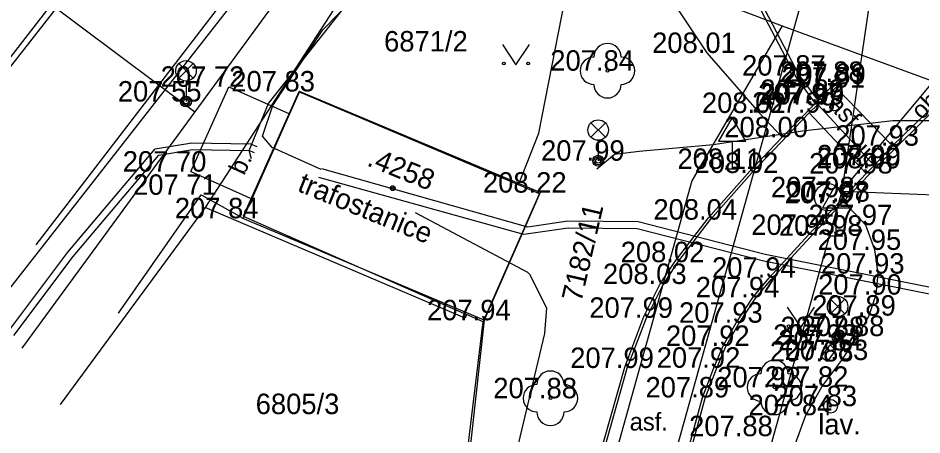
# Model space of a CAD drawing. Extents: x -524633 to -524336, y -1187893 to -1187683.
# Drawn here: x -524616 to -524582.86, y -1187820.09 to -1187804.81 of the extents above; entities that cross this region are included whole.
import ezdxf

# ---------------------------------------------------------------- set-up
doc = ezdxf.new("R2010")
doc.units = 0
for name, color, linetype in [('Hranice parcel', 7, 'Continuous'), ('Parcelní čísla', 7, 'Continuous'), ('Vrstva 1', 7, 'Continuous'), ('Vrstva 10', 7, 'Continuous'), ('Vrstva 11', 7, 'Continuous'), ('Vrstva 22', 7, 'Continuous'), ('Vrstva 24', 7, 'Continuous'), ('Vrstva 25', 7, 'Continuous'), ('Vrstva 27', 7, 'Continuous'), ('Vrstva 3', 7, 'Continuous'), ('Vrstva 33', 7, 'Continuous'), ('Vrstva 34', 7, 'Continuous'), ('Vrstva 36', 7, 'Continuous'), ('Vrstva 39', 7, 'Continuous'), ('Vrstva 4', 7, 'Continuous'), ('Vrstva 40', 7, 'Continuous'), ('Vrstva 41', 7, 'Continuous'), ('Vrstva 5', 7, 'Continuous'), ('Vrstva 52', 7, 'Continuous'), ('Vrstva 54', 7, 'Continuous'), ('Vrstva 55', 7, 'Continuous'), ('Vrstva 56', 7, 'Continuous'), ('Vrstva 7', 7, 'Continuous')]:
    doc.layers.add(name, color=color, linetype=linetype)

msp = doc.modelspace()

# ---------------------------------------------------------------- linework, layer by layer
at = {"layer": 'Hranice parcel'}
for p, q in [((-524601.49, -1187799.98), (-524609.14, -1187811.75)), ((-524595.57, -1187802.22), (-524587.98, -1187805.09)), ((-524587.98, -1187805.09), (-524591.3, -1187810.78)), ((-524609.14, -1187811.75), (-524614.452, -1187818.979)), ((-524599.61, -1187815.81), (-524609.14, -1187811.75)), ((-524599.56, -1187815.68), (-524599.61, -1187815.81)), ((-524598.94, -1187815.95), (-524599.56, -1187815.68))]:
    msp.add_line(p, q, dxfattribs=at)
for points in [[(-524587.98, -1187805.09), (-524567.6, -1187812.58), (-524548.29, -1187760.37)], [(-524597.65, -1187810.93), (-524596.9, -1187809.03), (-524595.57, -1187802.22)], [(-524597.65, -1187810.93), (-524605.7, -1187807.52), (-524607.75, -1187812.07), (-524599.56, -1187815.68)], [(-524591.3, -1187810.78), (-524596.74, -1187830.3), (-524599.279, -1187841.552)], [(-524598.94, -1187815.95), (-524596.88, -1187811.26), (-524597.65, -1187810.93)], [(-524601.622, -1187838.066), (-524598.94, -1187815.95)]]:
    msp.add_lwpolyline(points, dxfattribs=at)
at = {"layer": 'Vrstva 1'}
for p, q in [((-524590.75, -1187806.09), (-524590.75, -1187806.09)), ((-524594.39, -1187806.74), (-524594.39, -1187806.74)), ((-524587.36, -1187806.92), (-524587.36, -1187806.92)), ((-524585.97, -1187807.15), (-524585.97, -1187807.15)), ((-524585.89, -1187807.23), (-524585.89, -1187807.23)), ((-524608.27, -1187807.33), (-524608.27, -1187807.33)), ((-524605.68, -1187807.5), (-524605.68, -1187807.5)), ((-524586.01, -1187807.36), (-524586.01, -1187807.36)), ((-524609.84, -1187807.87), (-524609.84, -1187807.87)), ((-524586.69, -1187807.81), (-524586.69, -1187807.81)), ((-524586.77, -1187807.94), (-524586.77, -1187807.94)), ((-524586.68, -1187807.98), (-524586.68, -1187807.98)), ((-524588.83, -1187808.29), (-524588.83, -1187808.29)), ((-524586.99, -1187808.28), (-524586.99, -1187808.28)), ((-524587.98, -1187809.18), (-524587.98, -1187809.18)), ((-524583.94, -1187809.49), (-524583.94, -1187809.49)), ((-524594.73, -1187810.04), (-524594.73, -1187810.04)), ((-524584.61, -1187810.21), (-524584.61, -1187810.21)), ((-524609.66, -1187810.44), (-524609.66, -1187810.44)), ((-524589.82, -1187810.34), (-524589.82, -1187810.34)), ((-524589.1, -1187810.49), (-524589.1, -1187810.49)), ((-524584.9, -1187810.51), (-524584.9, -1187810.51)), ((-524584.59, -1187810.32), (-524584.59, -1187810.32)), ((-524596.86, -1187811.21), (-524596.86, -1187811.21)), ((-524609.28, -1187811.29), (-524609.28, -1187811.29)), ((-524586.3, -1187811.38), (-524586.3, -1187811.38)), ((-524585.74, -1187811.54), (-524585.74, -1187811.54)), ((-524585.8, -1187811.6), (-524585.8, -1187811.6)), ((-524607.75, -1187812.15), (-524607.75, -1187812.15)), ((-524590.61, -1187812.2), (-524590.61, -1187812.2)), ((-524584.92, -1187812.4), (-524584.92, -1187812.4)), ((-524587.02, -1187812.76), (-524587.02, -1187812.76)), ((-524586.01, -1187812.79), (-524586.01, -1187812.79)), ((-524584.59, -1187813.31), (-524584.59, -1187813.31)), ((-524591.81, -1187813.76), (-524591.81, -1187813.76)), ((-524584.47, -1187814.18), (-524584.47, -1187814.18)), ((-524588.46, -1187814.33), (-524588.46, -1187814.33)), ((-524592.46, -1187814.56), (-524592.46, -1187814.56)), ((-524589.06, -1187815.05), (-524589.06, -1187815.05)), ((-524584.54, -1187814.95), (-524584.54, -1187814.95)), ((-524592.96, -1187815.8), (-524592.96, -1187815.8)), ((-524584.79, -1187815.72), (-524584.79, -1187815.72)), ((-524598.91, -1187815.89), (-524598.91, -1187815.89)), ((-524589.67, -1187815.98), (-524589.67, -1187815.98)), ((-524585.95, -1187816.51), (-524585.95, -1187816.51)), ((-524585.21, -1187816.47), (-524585.21, -1187816.47)), ((-524590.15, -1187816.83), (-524590.15, -1187816.83)), ((-524586.22, -1187816.79), (-524586.22, -1187816.79)), ((-524586.03, -1187816.99), (-524586.03, -1187816.99)), ((-524586.34, -1187817.4), (-524586.34, -1187817.4)), ((-524585.8, -1187817.35), (-524585.8, -1187817.35)), ((-524593.66, -1187817.64), (-524593.66, -1187817.64)), ((-524590.49, -1187817.63), (-524590.49, -1187817.63)), ((-524588.27, -1187818.35), (-524588.27, -1187818.35)), ((-524586.53, -1187818.33), (-524586.53, -1187818.33)), ((-524596.48, -1187818.75), (-524596.48, -1187818.75)), ((-524590.9, -1187818.72), (-524590.9, -1187818.72)), ((-524586.21, -1187819.04), (-524586.21, -1187819.04)), ((-524587.12, -1187819.37), (-524587.12, -1187819.37))]:
    msp.add_line(p, q, dxfattribs=at)
at = {"layer": 'Vrstva 10'}
msp.add_line((-524619.041, -1187810.134), (-524610.724, -1187799.471), dxfattribs=at)
msp.add_lwpolyline([(-524607.4, -1187802.77), (-524615.342, -1187813.119)], dxfattribs=at)
at = {"layer": 'Vrstva 11'}
for p, q in [((-524580.79, -1187806.59), (-524584.589, -1187810.32)), ((-524609.66, -1187810.44), (-524608.27, -1187807.33)), ((-524608.27, -1187807.33), (-524606.045, -1187808.32)), ((-524609.66, -1187810.44), (-524607.431, -1187811.432))]:
    msp.add_line(p, q, dxfattribs=at)
for points in [[(-524597.4, -1187786.99), (-524593.539, -1187788.69), (-524593.099, -1187788.98), (-524592.909, -1187789.29), (-524592.87, -1187789.86), (-524593.639, -1187794.38), (-524593.659, -1187797.63), (-524593.279, -1187800.17), (-524592.58, -1187802.84), (-524591.989, -1187804.22), (-524590.75, -1187806.09), (-524588.83, -1187808.29), (-524587.979, -1187809.18)], [(-524584.279, -1187790.1), (-524589.16, -1187788.08), (-524589.906, -1187790.567), (-524590.419, -1187792.88), (-524590.639, -1187795.377), (-524590.669, -1187795.92), (-524590.54, -1187798.155), (-524589.955, -1187801.184), (-524589.619, -1187802.37), (-524588.89, -1187804.282), (-524587.47, -1187806.99), (-524586.77, -1187807.94), (-524586.68, -1187807.98), (-524586.01, -1187807.36), (-524585.889, -1187807.23), (-524585.969, -1187807.15)], [(-524584.17, -1187790.25), (-524589.08, -1187788.28), (-524589.78, -1187790.6), (-524590.29, -1187792.9), (-524590.509, -1187795.38), (-524590.511, -1187795.93), (-524590.41, -1187798.14), (-524589.829, -1187801.15), (-524589.46, -1187802.35), (-524588.77, -1187804.23), (-524587.36, -1187806.92), (-524586.689, -1187807.81), (-524585.969, -1187807.15)], [(-524580.79, -1187806.44), (-524583.939, -1187809.49)], [(-524583.939, -1187809.49), (-524586.01, -1187807.36)], [(-524598.029, -1187833.73), (-524596.837, -1187828.956), (-524596.356, -1187826.935), (-524595.036, -1187822.133), (-524593.755, -1187817.609), (-524593.05, -1187815.757), (-524592.459, -1187814.56), (-524591.894, -1187813.705), (-524590.686, -1187812.136), (-524589.173, -1187810.422), (-524587.979, -1187809.18), (-524586.77, -1187807.94)], [(-524597.94, -1187833.75), (-524596.74, -1187828.98), (-524596.259, -1187826.96), (-524594.94, -1187822.16), (-524593.66, -1187817.64), (-524592.959, -1187815.8), (-524592.367, -1187814.624), (-524591.81, -1187813.76), (-524590.609, -1187812.2), (-524589.099, -1187810.49), (-524586.99, -1187808.28), (-524586.68, -1187807.98)], [(-524584.609, -1187810.21), (-524586.68, -1187807.98)], [(-524586.99, -1187808.28), (-524584.899, -1187810.51)], [(-524583.939, -1187809.49), (-524584.609, -1187810.21)], [(-524584.609, -1187810.21), (-524584.9, -1187810.51)], [(-524595.18, -1187835.03), (-524592.989, -1187826.37), (-524590.899, -1187818.72), (-524590.489, -1187817.63), (-524590.149, -1187816.83), (-524589.669, -1187815.98), (-524589.059, -1187815.05), (-524588.459, -1187814.33), (-524587.019, -1187812.76), (-524584.9, -1187810.51)], [(-524595.083, -1187835.055), (-524594.02, -1187830.84), (-524593.84, -1187830.05), (-524593.019, -1187826.95), (-524592.893, -1187826.395), (-524590.804, -1187818.751), (-524590.396, -1187817.667), (-524590.059, -1187816.874), (-524589.584, -1187816.032), (-524588.979, -1187815.11), (-524588.384, -1187814.396), (-524586.946, -1187812.828), (-524585.8, -1187811.6), (-524585.74, -1187811.54), (-524584.59, -1187810.32)], [(-524584.369, -1187831.42), (-524584.929, -1187831), (-524585.72, -1187830.12), (-524586.199, -1187829.49), (-524586.74, -1187828.64), (-524587.34, -1187827.39), (-524587.86, -1187825.74), (-524588.049, -1187824.24), (-524588.05, -1187822.96), (-524587.9, -1187821.8), (-524587.69, -1187820.95), (-524587.119, -1187819.37), (-524586.53, -1187818.33), (-524585.8, -1187817.35), (-524585.209, -1187816.47), (-524584.789, -1187815.72), (-524584.539, -1187814.95), (-524584.469, -1187814.18), (-524584.59, -1187813.31), (-524584.92, -1187812.4), (-524585.739, -1187811.54)]]:
    msp.add_lwpolyline(points, dxfattribs=at)
at = {"layer": 'Vrstva 22'}
for centre in [(-524594.389, -1187806.74), (-524588.269, -1187818.35), (-524596.48, -1187818.75)]:
    msp.add_circle(centre, 0.05, dxfattribs=at)
for centre, start, end in [((-524594.389, -1187806.24), 0, 180), ((-524594.889, -1187806.74), 90, 270), ((-524593.889, -1187806.74), 270, 90), ((-524594.389, -1187807.24), 180, 0), ((-524588.269, -1187817.85), 0, 180), ((-524596.48, -1187818.25), 0, 180), ((-524588.769, -1187818.35), 90, 270), ((-524587.769, -1187818.35), 270, 90), ((-524596.98, -1187818.75), 90, 270), ((-524595.98, -1187818.75), 270, 90), ((-524588.269, -1187818.85), 180, 0), ((-524596.48, -1187819.25), 180, 0)]:
    msp.add_arc(centre, 0.5, start, end, dxfattribs=at)
at = {"layer": 'Vrstva 24'}
msp.add_lwpolyline([(-524586.219, -1187816.79), (-524586.029, -1187816.99), (-524586.339, -1187817.4), (-524586.553, -1187817.242), (-524586.219, -1187816.79)], dxfattribs=at)
at = {"layer": 'Vrstva 25'}
for radius in [0.25, 0.0303]:
    msp.add_circle((-524586.209, -1187819.04), radius, dxfattribs=at)
at = {"layer": 'Vrstva 27'}
msp.add_circle((-524586.299, -1187811.38), 0.5, dxfattribs=at)
at = {"layer": 'Vrstva 33'}
for p, q in [((-524610.105, -1187807.01), (-524609.575, -1187806.48)), ((-524610.105, -1187806.48), (-524609.575, -1187807.01)), ((-524609.84, -1187807.12), (-524609.84, -1187807.87)), ((-524594.995, -1187809.18), (-524594.465, -1187808.65)), ((-524594.995, -1187808.65), (-524594.465, -1187809.18)), ((-524594.73, -1187809.29), (-524594.73, -1187810.04)), ((-524586.214, -1187815.65), (-524585.684, -1187815.12)), ((-524586.214, -1187815.12), (-524585.684, -1187815.65)), ((-524585.949, -1187815.76), (-524585.949, -1187816.51))]:
    msp.add_line(p, q, dxfattribs=at)
for centre, radius in [((-524609.84, -1187806.745), 0.375), ((-524609.84, -1187807.87), 0.2), ((-524609.84, -1187807.87), 0.145), ((-524609.84, -1187807.87), 0.0876), ((-524594.73, -1187808.915), 0.375), ((-524594.73, -1187810.04), 0.2), ((-524594.73, -1187810.04), 0.145), ((-524594.73, -1187810.04), 0.0876), ((-524585.949, -1187815.385), 0.375), ((-524585.949, -1187816.51), 0.2), ((-524585.949, -1187816.51), 0.145), ((-524585.949, -1187816.51), 0.0876)]:
    msp.add_circle(centre, radius, dxfattribs=at)
at = {"layer": 'Vrstva 34'}
for p, q in [((-524589.82, -1187809.322), (-524589.82, -1187810.34)), ((-524590.07, -1187810.34), (-524589.57, -1187810.34)), ((-524586.01, -1187811.772), (-524586.01, -1187812.79)), ((-524586.26, -1187812.79), (-524585.76, -1187812.79))]:
    msp.add_line(p, q, dxfattribs=at)
for points in [[(-524590.32, -1187809.322), (-524589.32, -1187809.322), (-524589.82, -1187808.456)], [(-524586.51, -1187811.772), (-524585.51, -1187811.772), (-524586.01, -1187810.906)]]:
    msp.add_lwpolyline(points, close=True, dxfattribs=at)
at = {"layer": 'Vrstva 36'}
for points in [[(-524598.242, -1187805.778), (-524597.742, -1187806.528), (-524597.242, -1187805.778)], [(-524587.795, -1187815.407), (-524587.295, -1187816.157), (-524586.795, -1187815.407)]]:
    msp.add_lwpolyline(points, dxfattribs=at)
for centre in [(-524598.192, -1187806.477), (-524597.293, -1187806.477), (-524587.746, -1187816.107), (-524586.846, -1187816.107)]:
    msp.add_circle(centre, 0.05, dxfattribs=at)
at = {"layer": 'Vrstva 39'}
for radius in [0.09, 0.0398]:
    msp.add_circle((-524602.262, -1187811.048), radius, dxfattribs=at)
at = {"layer": 'Vrstva 5'}
for p, q in [((-524596.859, -1187811.21), (-524605.68, -1187807.5)), ((-524596.859, -1187811.21), (-524598.91, -1187815.89)), ((-524598.91, -1187815.89), (-524607.781, -1187812.15))]:
    msp.add_line(p, q, dxfattribs=at)
msp.add_lwpolyline([(-524605.68, -1187807.5), (-524606.045, -1187808.32), (-524607.431, -1187811.432), (-524607.75, -1187812.15)], dxfattribs=at)
at = {"layer": 'Vrstva 52'}
for points in [[(-524604.888, -1187810.358), (-524606.68, -1187809.553), (-524607.041, -1187809.142), (-524606.651, -1187808.01), (-524604.828, -1187805.241), (-524602.389, -1187802.751), (-524595.518, -1187792.842), (-524592.363, -1187786.571), (-524587.685, -1187773.341), (-524584.851, -1187764.936), (-524580.85, -1187751.486), (-524581.943, -1187749.433), (-524589.511, -1187743.31), (-524591.925, -1187742.225), (-524592.398, -1187741.002), (-524589.2, -1187727.331), (-524588.107, -1187723.138), (-524586.572, -1187712.872)], [(-524607.441, -1187809.976), (-524607.53, -1187809.669), (-524606.817, -1187807.941), (-524600.734, -1187800.222), (-524596.921, -1187794.77), (-524594.569, -1187790.848), (-524590.203, -1187780.476), (-524585.928, -1187767.436), (-524582.597, -1187756.424), (-524580.946, -1187751.47), (-524581.141, -1187750.169), (-524583.06, -1187749.051), (-524585.106, -1187746.981), (-524589.425, -1187743.717), (-524592.03, -1187742.347), (-524592.569, -1187741.747), (-524592.712, -1187740.711), (-524590.247, -1187725.964), (-524590.389, -1187724.462)], [(-524561.344, -1187803.955), (-524561.158, -1187804.072), (-524561.105, -1187804.363), (-524560.563, -1187805.046), (-524565.022, -1187808.878), (-524568.246, -1187812.343), (-524571.77, -1187815.678), (-524574.968, -1187815.882), (-524582.642, -1187814.923), (-524588.661, -1187813.718), (-524593.294, -1187812.534), (-524595.823, -1187812.509), (-524597.459, -1187812.746), (-524604.971, -1187810.656)], [(-524594.78, -1187810.34), (-524594.13, -1187809.8), (-524593.22, -1187809.69), (-524590.51, -1187809.44), (-524587.24, -1187808.95), (-524583.93, -1187808.57), (-524582.42, -1187808.56)], [(-524594.78, -1187810.34), (-524594.13, -1187809.8), (-524593.22, -1187809.69), (-524590.51, -1187809.44), (-524587.24, -1187808.95), (-524583.93, -1187808.57), (-524582.42, -1187808.56)], [(-524616.301, -1187816.226), (-524614.173, -1187813.398), (-524610.969, -1187809.609), (-524609.623, -1187809.38), (-524607.479, -1187809.42), (-524607.248, -1187809.513)], [(-524616.154, -1187816.446), (-524613.978, -1187813.554), (-524610.837, -1187809.84), (-524609.604, -1187809.63), (-524607.53, -1187809.669), (-524607.344, -1187809.744)], [(-524582.602, -1187814.676), (-524588.605, -1187813.474), (-524593.261, -1187812.284), (-524595.84, -1187812.259), (-524597.308, -1187812.473), (-524604.865, -1187810.336)], [(-524601.437, -1187811.944), (-524597.315, -1187814.128), (-524597.244, -1187814.198), (-524596.619, -1187815.437), (-524596.693, -1187816.369), (-524597.904, -1187821.455), (-524598.998, -1187827.91), (-524599.45, -1187831), (-524600.062, -1187834.455), (-524600.26, -1187836.252), (-524600.682, -1187839.465)]]:
    msp.add_lwpolyline(points, dxfattribs=at)
at = {"layer": 'Vrstva 54'}
for p, q in [((-524615.844, -1187816.907), (-524598.973, -1187793.847)), ((-524609.518, -1187808.261), (-524617.317, -1187802.419))]:
    msp.add_line(p, q, dxfattribs=at)
at = {"layer": 'Vrstva 55'}
for p, q in [((-524585.8, -1187811.16), (-524537.22, -1187752.94)), ((-524604.019, -1187798.98), (-524616.853, -1187815.406)), ((-524586.38, -1187800.98), (-524594.57, -1187830.29)), ((-524584.4, -1187801.59), (-524585.8, -1187811.16)), ((-524585.8, -1187811.16), (-524595.769, -1187846.775)), ((-524585.8, -1187811.16), (-524580.804, -1187811.357))]:
    msp.add_line(p, q, dxfattribs=at)
at = {"layer": 'Vrstva 56'}
msp.add_lwpolyline([(-524586.54, -1187727.18), (-524588.97, -1187737.12), (-524590.36, -1187742.45), (-524593, -1187751.96), (-524600.51, -1187779.94), (-524604.9, -1187791.29), (-524607.89, -1187795.49), (-524608.098, -1187795.783), (-524608.38, -1187796.18), (-524608.59, -1187796.44), (-524610.16, -1187798.34), (-524617.66, -1187808), (-524619.897, -1187810.877)], dxfattribs=at)
at = {"layer": 'Vrstva 7'}
for p, q in [((-524612.317, -1187815.63), (-524609.28, -1187811.29)), ((-524609.28, -1187811.29), (-524607.75, -1187812.15))]:
    msp.add_line(p, q, dxfattribs=at)
msp.add_lwpolyline([(-524598.91, -1187815.89), (-524599.739, -1187823.43)], dxfattribs=at)

# ---------------------------------------------------------------- texts
at = {"layer": 'Parcelní čísla'}
for s, p in [('6871/2', (-524602.578, -1187806.035)), ('6805/3', (-524607.285, -1187819.33))]:
    msp.add_text(s, height=0.75, dxfattribs=at).set_placement(p)
for s, rotation, p in [('.4258', 338, (-524603.244, -1187810.205)), ('7182/11', 77, (-524595.346, -1187815.25))]:
    msp.add_text(s, height=0.75, rotation=rotation, dxfattribs=at).set_placement(p)
at = {"layer": 'Vrstva 3'}
for s, p in [('207.84', (-524596.484, -1187806.74)), ('207.89', (-524587.984, -1187807.23)), ('208.00', (-524590.104, -1187809.18)), ('207.99', (-524586.704, -1187810.21)), ('208.22', (-524598.954, -1187811.21)), ('207.98', (-524587.834, -1187811.54)), ('207.95', (-524586.685, -1187813.31)), ('208.03', (-524594.554, -1187814.56)), ('207.94', (-524601.004, -1187815.89)), ('207.93', (-524591.764, -1187815.98)), ('207.92', (-524592.584, -1187817.63)), ('207.88', (-524598.574, -1187818.75)), ('207.83', (-524588.304, -1187819.04))]:
    msp.add_text(s, height=0.75, dxfattribs=at).set_placement(p)
at = {"layer": 'Vrstva 4'}
for s, p in [('208.01', (-524592.75, -1187806.09)), ('207.87', (-524589.454, -1187806.92)), ('207 72 ', (-524610.77, -1187807.33)), ('207.88', (-524588.064, -1187807.15)), ('207 83 ', (-524608.18, -1187807.5)), ('207.91', (-524588.01, -1187807.36)), ('207 55 ', (-524612.34, -1187807.87)), ('207.97', (-524588.864, -1187807.94)), ('207.89', (-524588.784, -1187807.81)), ('207.99', (-524588.774, -1187807.98)), ('208.02', (-524590.924, -1187808.29)), ('207.99', (-524589.084, -1187808.28)), ('207.93', (-524586.034, -1187809.49)), ('207.99', (-524596.824, -1187810.04)), ('208.00', (-524586.714, -1187810.32)), ('207 70 ', (-524612.16, -1187810.44)), ('208.11', (-524591.82, -1187810.34)), ('208.02', (-524591.194, -1187810.49)), ('207.98', (-524586.994, -1187810.51)), ('207 71 ', (-524611.78, -1187811.29)), ('207.98', (-524588.394, -1187811.38)), ('207.97', (-524587.894, -1187811.6)), ('207 84 ', (-524610.25, -1187812.15)), ('208.04', (-524592.704, -1187812.2)), ('207.97', (-524587.014, -1187812.4)), ('207.95', (-524589.115, -1187812.76)), ('207.98', (-524588.104, -1187812.79)), ('208.02', (-524593.904, -1187813.76)), ('207.93', (-524586.564, -1187814.18)), ('207.94', (-524590.554, -1187814.33)), ('207.90', (-524586.664, -1187814.95)), ('207.94', (-524591.154, -1187815.05)), ('207.99', (-524595.054, -1187815.8)), ('207.89', (-524586.884, -1187815.72)), ('207.88', (-524588.044, -1187816.51)), ('207.88', (-524587.304, -1187816.47)), ('207.92', (-524592.244, -1187816.83)), ('207.93', (-524588.314, -1187816.79)), ('207.84', (-524588.124, -1187816.99)), ('207.83', (-524588.434, -1187817.4)), ('207.83', (-524587.894, -1187817.35)), ('207.99', (-524595.754, -1187817.64)), ('207.92', (-524590.364, -1187818.35)), ('207.82', (-524588.624, -1187818.33)), ('207.89', (-524592.994, -1187818.72)), ('207.84', (-524589.214, -1187819.37)), ('207.88', (-524591.394, -1187820.14))]:
    msp.add_text(s, height=0.75, dxfattribs=at).set_placement(p)
at = {"layer": 'Vrstva 40'}
for s, rotation, p in [('obr.', 44.0828, (-524582.87, -1187808.572)), ('asf.', 314.192, (-524586.335, -1187808.038)), ('dl.', 314.192, (-524585.654, -1187809.659)), ('b.', 65.1149, (-524607.708, -1187810.604))]:
    msp.add_text(s, height=0.65, rotation=rotation, dxfattribs=at).set_placement(p)
msp.add_text('asf.', height=0.65, dxfattribs=at).set_placement((-524593.573, -1187819.933))
at = {"layer": 'Vrstva 41'}
msp.add_text('trafostanice', height=0.75, rotation=337.7554, dxfattribs=at).set_placement((-524605.795, -1187811.138))
msp.add_text('lav.', height=0.75, dxfattribs=at).set_placement((-524586.658, -1187820.078))

doc.saveas('drawing.dxf')
